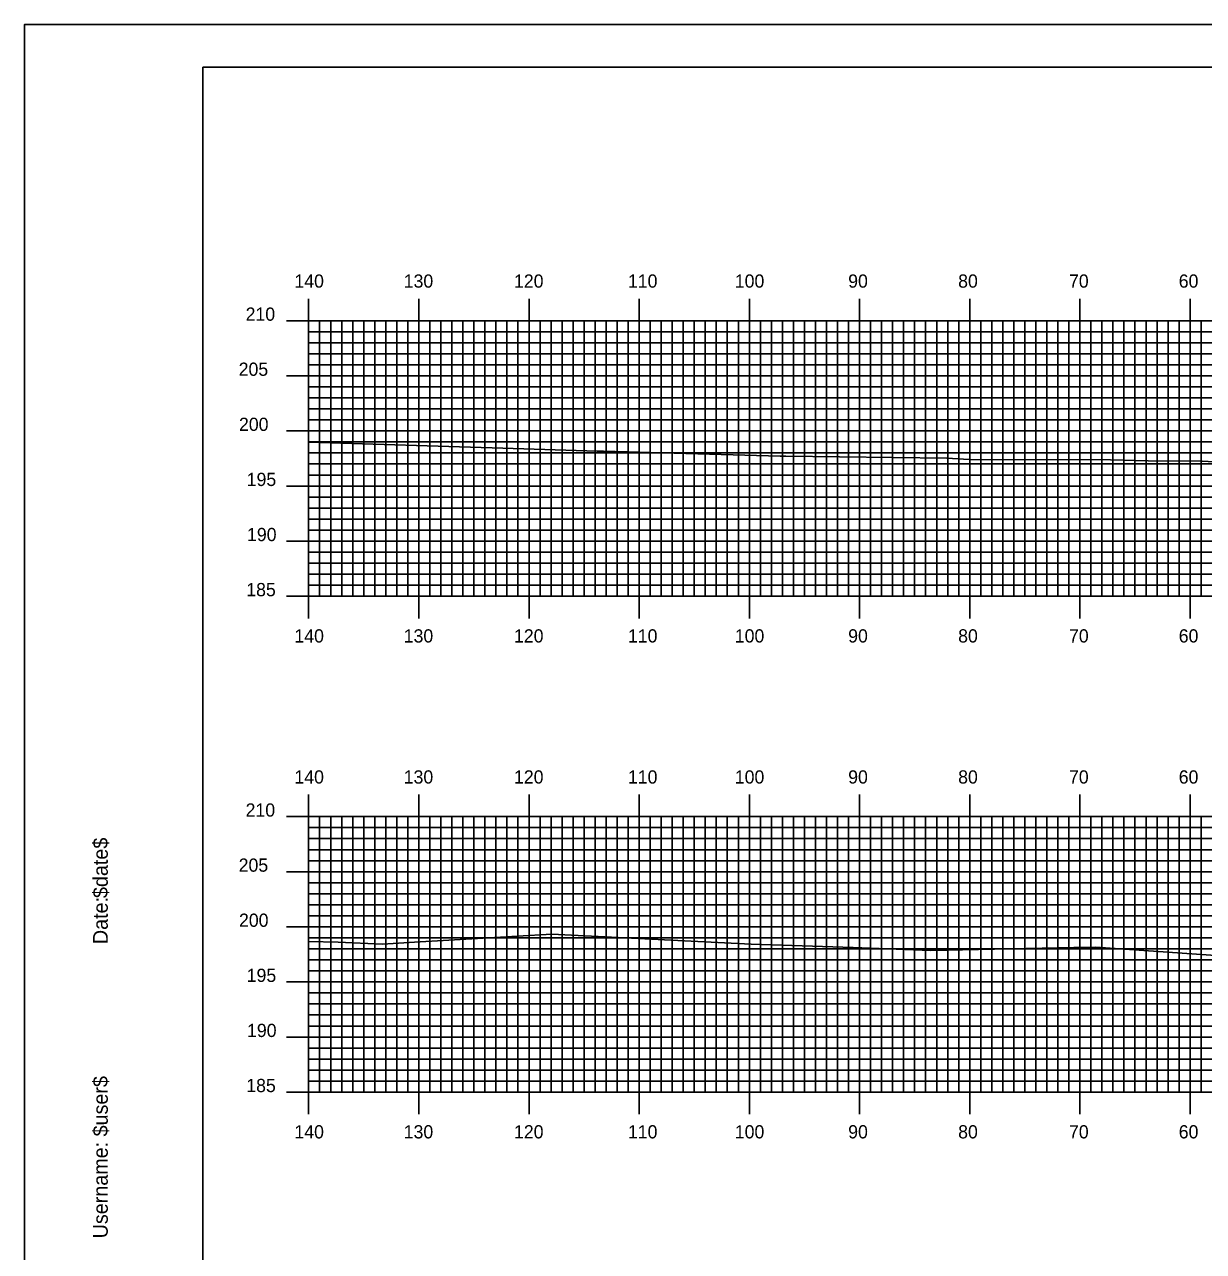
# Model space of a CAD drawing. Extents: x 1813735 to 1814078, y 442591 to 442811.
# Drawn here: x 1813734.7 to 1813841.7, y 442699.2 to 442810.5 of the extents above; entities that cross this region are included whole.
import ezdxf

# ---------------------------------------------------------------- set-up
doc = ezdxf.new("R2010")
doc.units = 0
for name, color, linetype in [('BORDER', 7, 'Continuous'), ('H_V ANNOTATION', 7, 'Continuous'), ('MAJOR', 7, 'Continuous'), ('MINOR', 7, 'Continuous'), ('PLOT BOUNDARY', 7, 'Continuous'), ('S_Roadway_Centerline', 7, 'Continuous')]:
    doc.layers.add(name, color=color, linetype=linetype)

msp = doc.modelspace()

# ---------------------------------------------------------------- linework, layer by layer
at = {"layer": 'BORDER'}
msp.add_lwpolyline([(1813750.88, 442596.67), (1814070.88, 442596.67), (1814070.88, 442806.67), (1813750.88, 442806.67)], close=True, dxfattribs=at)
at = {"layer": 'MAJOR'}
for p, q in [((1813760.48, 442785.67), (1813760.48, 442783.67)), ((1813770.48, 442785.67), (1813770.48, 442783.67)), ((1813780.48, 442785.67), (1813780.48, 442783.67)), ((1813790.48, 442785.67), (1813790.48, 442783.67)), ((1813800.48, 442785.67), (1813800.48, 442783.67)), ((1813810.48, 442785.67), (1813810.48, 442783.67)), ((1813820.48, 442785.67), (1813820.48, 442783.67)), ((1813830.48, 442785.67), (1813830.48, 442783.67)), ((1813840.48, 442785.67), (1813840.48, 442783.67)), ((1813758.48, 442783.67), (1813760.48, 442783.67)), ((1813760.48, 442783.67), (1814040.48, 442783.67)), ((1813760.48, 442758.67), (1813760.48, 442783.67)), ((1813760.48, 442758.67), (1813760.48, 442783.67)), ((1813760.48, 442783.67), (1814040.48, 442783.67)), ((1813770.48, 442758.67), (1813770.48, 442783.67)), ((1813780.48, 442758.67), (1813780.48, 442783.67)), ((1813790.48, 442758.67), (1813790.48, 442783.67)), ((1813800.48, 442758.67), (1813800.48, 442783.67)), ((1813810.48, 442758.67), (1813810.48, 442783.67)), ((1813820.48, 442758.67), (1813820.48, 442783.67)), ((1813830.48, 442758.67), (1813830.48, 442783.67)), ((1813840.48, 442758.67), (1813840.48, 442783.67)), ((1813758.48, 442778.67), (1813760.48, 442778.67)), ((1813760.48, 442778.67), (1814040.48, 442778.67)), ((1813758.48, 442773.67), (1813760.48, 442773.67)), ((1813760.48, 442773.67), (1814040.48, 442773.67)), ((1813758.48, 442768.67), (1813760.48, 442768.67)), ((1813760.48, 442768.67), (1814040.48, 442768.67)), ((1813758.48, 442763.67), (1813760.48, 442763.67)), ((1813760.48, 442763.67), (1814040.48, 442763.67)), ((1813758.48, 442758.67), (1813760.48, 442758.67)), ((1813760.48, 442758.67), (1814040.48, 442758.67)), ((1813760.48, 442758.67), (1814040.48, 442758.67)), ((1813760.48, 442756.66), (1813760.48, 442758.67)), ((1813770.48, 442756.66), (1813770.48, 442758.67)), ((1813780.48, 442756.66), (1813780.48, 442758.67)), ((1813790.48, 442756.66), (1813790.48, 442758.67)), ((1813800.48, 442756.66), (1813800.48, 442758.67)), ((1813810.48, 442756.66), (1813810.48, 442758.67)), ((1813820.48, 442756.66), (1813820.48, 442758.67)), ((1813830.48, 442756.66), (1813830.48, 442758.67)), ((1813840.48, 442756.66), (1813840.48, 442758.67)), ((1813760.48, 442740.67), (1813760.48, 442738.67)), ((1813770.48, 442740.67), (1813770.48, 442738.67)), ((1813780.48, 442740.67), (1813780.48, 442738.67)), ((1813790.48, 442740.67), (1813790.48, 442738.67)), ((1813800.48, 442740.67), (1813800.48, 442738.67)), ((1813810.48, 442740.67), (1813810.48, 442738.67)), ((1813820.48, 442740.67), (1813820.48, 442738.67)), ((1813830.48, 442740.67), (1813830.48, 442738.67)), ((1813840.48, 442740.67), (1813840.48, 442738.67)), ((1813758.48, 442738.67), (1813760.48, 442738.67)), ((1813760.48, 442738.67), (1814040.48, 442738.67)), ((1813760.48, 442713.67), (1813760.48, 442738.67)), ((1813760.48, 442713.67), (1813760.48, 442738.67)), ((1813760.48, 442738.67), (1814040.48, 442738.67)), ((1813770.48, 442713.67), (1813770.48, 442738.67)), ((1813780.48, 442713.67), (1813780.48, 442738.67)), ((1813790.48, 442713.67), (1813790.48, 442738.67)), ((1813800.48, 442713.67), (1813800.48, 442738.67)), ((1813810.48, 442713.67), (1813810.48, 442738.67)), ((1813820.48, 442713.67), (1813820.48, 442738.67)), ((1813830.48, 442713.67), (1813830.48, 442738.67)), ((1813840.48, 442713.67), (1813840.48, 442738.67)), ((1813758.48, 442733.67), (1813760.48, 442733.67)), ((1813760.48, 442733.67), (1814040.48, 442733.67)), ((1813758.48, 442728.67), (1813760.48, 442728.67)), ((1813760.48, 442728.67), (1814040.48, 442728.67)), ((1813758.48, 442723.67), (1813760.48, 442723.67)), ((1813760.48, 442723.67), (1814040.48, 442723.67)), ((1813758.48, 442718.67), (1813760.48, 442718.67)), ((1813760.48, 442718.67), (1814040.48, 442718.67)), ((1813758.48, 442713.67), (1813760.48, 442713.67)), ((1813760.48, 442713.67), (1814040.48, 442713.67)), ((1813760.48, 442713.67), (1814040.48, 442713.67)), ((1813760.48, 442711.66), (1813760.48, 442713.67)), ((1813770.48, 442711.66), (1813770.48, 442713.67)), ((1813780.48, 442711.66), (1813780.48, 442713.67)), ((1813790.48, 442711.66), (1813790.48, 442713.67)), ((1813800.48, 442711.66), (1813800.48, 442713.67)), ((1813810.48, 442711.66), (1813810.48, 442713.67)), ((1813820.48, 442711.66), (1813820.48, 442713.67)), ((1813830.48, 442711.66), (1813830.48, 442713.67)), ((1813840.48, 442711.66), (1813840.48, 442713.67))]:
    msp.add_line(p, q, dxfattribs=at)
at = {"layer": 'MINOR'}
for p, q in [((1813761.48, 442758.67), (1813761.48, 442783.67)), ((1813762.48, 442758.67), (1813762.48, 442783.67)), ((1813763.48, 442758.67), (1813763.48, 442783.67)), ((1813764.48, 442758.67), (1813764.48, 442783.67)), ((1813765.48, 442758.67), (1813765.48, 442783.67)), ((1813766.48, 442758.67), (1813766.48, 442783.67)), ((1813767.48, 442758.67), (1813767.48, 442783.67)), ((1813768.48, 442758.67), (1813768.48, 442783.67)), ((1813769.48, 442758.67), (1813769.48, 442783.67)), ((1813771.48, 442758.67), (1813771.48, 442783.67)), ((1813772.48, 442758.67), (1813772.48, 442783.67)), ((1813773.48, 442758.67), (1813773.48, 442783.67)), ((1813774.48, 442758.67), (1813774.48, 442783.67)), ((1813775.48, 442758.67), (1813775.48, 442783.67)), ((1813776.48, 442758.67), (1813776.48, 442783.67)), ((1813777.48, 442758.67), (1813777.48, 442783.67)), ((1813778.48, 442758.67), (1813778.48, 442783.67)), ((1813779.48, 442758.67), (1813779.48, 442783.67)), ((1813781.48, 442758.67), (1813781.48, 442783.67)), ((1813782.48, 442758.67), (1813782.48, 442783.67)), ((1813783.48, 442758.67), (1813783.48, 442783.67)), ((1813784.48, 442758.67), (1813784.48, 442783.67)), ((1813785.48, 442758.67), (1813785.48, 442783.67)), ((1813786.48, 442758.67), (1813786.48, 442783.67)), ((1813787.48, 442758.67), (1813787.48, 442783.67)), ((1813788.48, 442758.67), (1813788.48, 442783.67)), ((1813789.48, 442758.67), (1813789.48, 442783.67)), ((1813791.48, 442758.67), (1813791.48, 442783.67)), ((1813792.48, 442758.67), (1813792.48, 442783.67)), ((1813793.48, 442758.67), (1813793.48, 442783.67)), ((1813794.48, 442758.67), (1813794.48, 442783.67)), ((1813795.48, 442758.67), (1813795.48, 442783.67)), ((1813796.48, 442758.67), (1813796.48, 442783.67)), ((1813797.48, 442758.67), (1813797.48, 442783.67)), ((1813798.48, 442758.67), (1813798.48, 442783.67)), ((1813799.48, 442758.67), (1813799.48, 442783.67)), ((1813801.48, 442758.67), (1813801.48, 442783.67)), ((1813802.48, 442758.67), (1813802.48, 442783.67)), ((1813803.48, 442758.67), (1813803.48, 442783.67)), ((1813804.48, 442758.67), (1813804.48, 442783.67)), ((1813805.48, 442758.67), (1813805.48, 442783.67)), ((1813806.48, 442758.67), (1813806.48, 442783.67)), ((1813807.48, 442758.67), (1813807.48, 442783.67)), ((1813808.48, 442758.67), (1813808.48, 442783.67)), ((1813809.48, 442758.67), (1813809.48, 442783.67)), ((1813811.48, 442758.67), (1813811.48, 442783.67)), ((1813812.48, 442758.67), (1813812.48, 442783.67)), ((1813813.48, 442758.67), (1813813.48, 442783.67)), ((1813814.48, 442758.67), (1813814.48, 442783.67)), ((1813815.48, 442758.67), (1813815.48, 442783.67)), ((1813816.48, 442758.67), (1813816.48, 442783.67)), ((1813817.48, 442758.67), (1813817.48, 442783.67)), ((1813818.48, 442758.67), (1813818.48, 442783.67)), ((1813819.48, 442758.67), (1813819.48, 442783.67)), ((1813821.48, 442758.67), (1813821.48, 442783.67)), ((1813822.48, 442758.67), (1813822.48, 442783.67)), ((1813823.48, 442758.67), (1813823.48, 442783.67)), ((1813824.48, 442758.67), (1813824.48, 442783.67)), ((1813825.48, 442758.67), (1813825.48, 442783.67)), ((1813826.48, 442758.67), (1813826.48, 442783.67)), ((1813827.48, 442758.67), (1813827.48, 442783.67)), ((1813828.48, 442758.67), (1813828.48, 442783.67)), ((1813829.48, 442758.67), (1813829.48, 442783.67)), ((1813831.48, 442758.67), (1813831.48, 442783.67)), ((1813832.48, 442758.67), (1813832.48, 442783.67)), ((1813833.48, 442758.67), (1813833.48, 442783.67)), ((1813834.48, 442758.67), (1813834.48, 442783.67)), ((1813835.48, 442758.67), (1813835.48, 442783.67)), ((1813836.48, 442758.67), (1813836.48, 442783.67)), ((1813837.48, 442758.67), (1813837.48, 442783.67)), ((1813838.48, 442758.67), (1813838.48, 442783.67)), ((1813839.48, 442758.67), (1813839.48, 442783.67)), ((1813841.48, 442758.67), (1813841.48, 442783.67)), ((1813760.48, 442782.67), (1814040.48, 442782.67)), ((1813760.48, 442782.67), (1813762.49, 442782.67)), ((1813760.48, 442781.67), (1814040.48, 442781.67)), ((1813760.48, 442781.67), (1813762.49, 442781.67)), ((1813760.48, 442780.67), (1814040.48, 442780.67)), ((1813760.48, 442780.67), (1813762.49, 442780.67)), ((1813760.48, 442779.67), (1814040.48, 442779.67)), ((1813760.48, 442779.67), (1813762.49, 442779.67)), ((1813760.48, 442777.67), (1814040.48, 442777.67)), ((1813760.48, 442777.67), (1813762.49, 442777.67)), ((1813760.48, 442776.67), (1814040.48, 442776.67)), ((1813760.48, 442776.67), (1813762.49, 442776.67)), ((1813760.48, 442775.67), (1814040.48, 442775.67)), ((1813760.48, 442775.67), (1813762.49, 442775.67)), ((1813760.48, 442774.67), (1814040.48, 442774.67)), ((1813760.48, 442774.67), (1813762.49, 442774.67)), ((1813760.48, 442772.67), (1814040.48, 442772.67)), ((1813760.48, 442772.67), (1813762.49, 442772.67)), ((1813760.48, 442771.67), (1814040.48, 442771.67)), ((1813760.48, 442771.67), (1813762.49, 442771.67)), ((1813760.48, 442770.67), (1814040.48, 442770.67)), ((1813760.48, 442770.67), (1813762.49, 442770.67)), ((1813760.48, 442769.67), (1814040.48, 442769.67)), ((1813760.48, 442769.67), (1813762.49, 442769.67)), ((1813760.48, 442767.67), (1814040.48, 442767.67)), ((1813760.48, 442767.67), (1813762.49, 442767.67)), ((1813760.48, 442766.67), (1814040.48, 442766.67)), ((1813760.48, 442766.67), (1813762.49, 442766.67)), ((1813760.48, 442765.67), (1814040.48, 442765.67)), ((1813760.48, 442765.67), (1813762.49, 442765.67)), ((1813760.48, 442764.67), (1814040.48, 442764.67)), ((1813760.48, 442764.67), (1813762.49, 442764.67)), ((1813760.48, 442762.67), (1814040.48, 442762.67)), ((1813760.48, 442762.67), (1813762.49, 442762.67)), ((1813760.48, 442761.67), (1814040.48, 442761.67)), ((1813760.48, 442761.67), (1813762.49, 442761.67)), ((1813760.48, 442760.67), (1814040.48, 442760.67)), ((1813760.48, 442760.67), (1813762.49, 442760.67)), ((1813760.48, 442759.67), (1814040.48, 442759.67)), ((1813760.48, 442759.67), (1813762.49, 442759.67)), ((1813761.48, 442713.67), (1813761.48, 442738.67)), ((1813762.48, 442713.67), (1813762.48, 442738.67)), ((1813763.48, 442713.67), (1813763.48, 442738.67)), ((1813764.48, 442713.67), (1813764.48, 442738.67)), ((1813765.48, 442713.67), (1813765.48, 442738.67)), ((1813766.48, 442713.67), (1813766.48, 442738.67)), ((1813767.48, 442713.67), (1813767.48, 442738.67)), ((1813768.48, 442713.67), (1813768.48, 442738.67)), ((1813769.48, 442713.67), (1813769.48, 442738.67)), ((1813771.48, 442713.67), (1813771.48, 442738.67)), ((1813772.48, 442713.67), (1813772.48, 442738.67)), ((1813773.48, 442713.67), (1813773.48, 442738.67)), ((1813774.48, 442713.67), (1813774.48, 442738.67)), ((1813775.48, 442713.67), (1813775.48, 442738.67)), ((1813776.48, 442713.67), (1813776.48, 442738.67)), ((1813777.48, 442713.67), (1813777.48, 442738.67)), ((1813778.48, 442713.67), (1813778.48, 442738.67)), ((1813779.48, 442713.67), (1813779.48, 442738.67)), ((1813781.48, 442713.67), (1813781.48, 442738.67)), ((1813782.48, 442713.67), (1813782.48, 442738.67)), ((1813783.48, 442713.67), (1813783.48, 442738.67)), ((1813784.48, 442713.67), (1813784.48, 442738.67)), ((1813785.48, 442713.67), (1813785.48, 442738.67)), ((1813786.48, 442713.67), (1813786.48, 442738.67)), ((1813787.48, 442713.67), (1813787.48, 442738.67)), ((1813788.48, 442713.67), (1813788.48, 442738.67)), ((1813789.48, 442713.67), (1813789.48, 442738.67)), ((1813791.48, 442713.67), (1813791.48, 442738.67)), ((1813792.48, 442713.67), (1813792.48, 442738.67)), ((1813793.48, 442713.67), (1813793.48, 442738.67)), ((1813794.48, 442713.67), (1813794.48, 442738.67)), ((1813795.48, 442713.67), (1813795.48, 442738.67)), ((1813796.48, 442713.67), (1813796.48, 442738.67)), ((1813797.48, 442713.67), (1813797.48, 442738.67)), ((1813798.48, 442713.67), (1813798.48, 442738.67)), ((1813799.48, 442713.67), (1813799.48, 442738.67)), ((1813801.48, 442713.67), (1813801.48, 442738.67)), ((1813802.48, 442713.67), (1813802.48, 442738.67)), ((1813803.48, 442713.67), (1813803.48, 442738.67)), ((1813804.48, 442713.67), (1813804.48, 442738.67)), ((1813805.48, 442713.67), (1813805.48, 442738.67)), ((1813806.48, 442713.67), (1813806.48, 442738.67)), ((1813807.48, 442713.67), (1813807.48, 442738.67)), ((1813808.48, 442713.67), (1813808.48, 442738.67)), ((1813809.48, 442713.67), (1813809.48, 442738.67)), ((1813811.48, 442713.67), (1813811.48, 442738.67)), ((1813812.48, 442713.67), (1813812.48, 442738.67)), ((1813813.48, 442713.67), (1813813.48, 442738.67)), ((1813814.48, 442713.67), (1813814.48, 442738.67)), ((1813815.48, 442713.67), (1813815.48, 442738.67)), ((1813816.48, 442713.67), (1813816.48, 442738.67)), ((1813817.48, 442713.67), (1813817.48, 442738.67)), ((1813818.48, 442713.67), (1813818.48, 442738.67)), ((1813819.48, 442713.67), (1813819.48, 442738.67)), ((1813821.48, 442713.67), (1813821.48, 442738.67)), ((1813822.48, 442713.67), (1813822.48, 442738.67)), ((1813823.48, 442713.67), (1813823.48, 442738.67)), ((1813824.48, 442713.67), (1813824.48, 442738.67)), ((1813825.48, 442713.67), (1813825.48, 442738.67)), ((1813826.48, 442713.67), (1813826.48, 442738.67)), ((1813827.48, 442713.67), (1813827.48, 442738.67)), ((1813828.48, 442713.67), (1813828.48, 442738.67)), ((1813829.48, 442713.67), (1813829.48, 442738.67)), ((1813831.48, 442713.67), (1813831.48, 442738.67)), ((1813832.48, 442713.67), (1813832.48, 442738.67)), ((1813833.48, 442713.67), (1813833.48, 442738.67)), ((1813834.48, 442713.67), (1813834.48, 442738.67)), ((1813835.48, 442713.67), (1813835.48, 442738.67)), ((1813836.48, 442713.67), (1813836.48, 442738.67)), ((1813837.48, 442713.67), (1813837.48, 442738.67)), ((1813838.48, 442713.67), (1813838.48, 442738.67)), ((1813839.48, 442713.67), (1813839.48, 442738.67)), ((1813841.48, 442713.67), (1813841.48, 442738.67)), ((1813760.48, 442737.67), (1814040.48, 442737.67)), ((1813760.48, 442737.67), (1813762.49, 442737.67)), ((1813760.48, 442736.67), (1814040.48, 442736.67)), ((1813760.48, 442736.67), (1813762.49, 442736.67)), ((1813760.48, 442735.67), (1814040.48, 442735.67)), ((1813760.48, 442735.67), (1813762.49, 442735.67)), ((1813760.48, 442734.67), (1814040.48, 442734.67)), ((1813760.48, 442734.67), (1813762.49, 442734.67)), ((1813760.48, 442732.67), (1814040.48, 442732.67)), ((1813760.48, 442732.67), (1813762.49, 442732.67)), ((1813760.48, 442731.67), (1814040.48, 442731.67)), ((1813760.48, 442731.67), (1813762.49, 442731.67)), ((1813760.48, 442730.67), (1814040.48, 442730.67)), ((1813760.48, 442730.67), (1813762.49, 442730.67)), ((1813760.48, 442729.67), (1814040.48, 442729.67)), ((1813760.48, 442729.67), (1813762.49, 442729.67)), ((1813760.48, 442727.67), (1814040.48, 442727.67)), ((1813760.48, 442727.67), (1813762.49, 442727.67)), ((1813760.48, 442726.67), (1814040.48, 442726.67)), ((1813760.48, 442726.67), (1813762.49, 442726.67)), ((1813760.48, 442725.67), (1814040.48, 442725.67)), ((1813760.48, 442725.67), (1813762.49, 442725.67)), ((1813760.48, 442724.67), (1814040.48, 442724.67)), ((1813760.48, 442724.67), (1813762.49, 442724.67)), ((1813760.48, 442722.67), (1814040.48, 442722.67)), ((1813760.48, 442722.67), (1813762.49, 442722.67)), ((1813760.48, 442721.67), (1814040.48, 442721.67)), ((1813760.48, 442721.67), (1813762.49, 442721.67)), ((1813760.48, 442720.67), (1814040.48, 442720.67)), ((1813760.48, 442720.67), (1813762.49, 442720.67)), ((1813760.48, 442719.67), (1814040.48, 442719.67)), ((1813760.48, 442719.67), (1813762.49, 442719.67)), ((1813760.48, 442717.67), (1814040.48, 442717.67)), ((1813760.48, 442717.67), (1813762.49, 442717.67)), ((1813760.48, 442716.67), (1814040.48, 442716.67)), ((1813760.48, 442716.67), (1813762.49, 442716.67)), ((1813760.48, 442715.67), (1814040.48, 442715.67)), ((1813760.48, 442715.67), (1813762.49, 442715.67)), ((1813760.48, 442714.67), (1814040.48, 442714.67)), ((1813760.48, 442714.67), (1813762.49, 442714.67))]:
    msp.add_line(p, q, dxfattribs=at)
at = {"layer": 'PLOT BOUNDARY'}
msp.add_lwpolyline([(1813734.69, 442590.55), (1814074.69, 442590.55), (1814074.69, 442810.55), (1813734.69, 442810.55)], close=True, dxfattribs=at)
at = {"layer": 'S_Roadway_Centerline'}
for points in [[(1813760.48, 442772.66), (1813778.12, 442772.11), (1813786.67, 442771.82), (1813787.25, 442771.82), (1813803.28, 442771.39), (1813803.78, 442771.39), (1813818.39, 442771.2), (1813820.44, 442771.08), (1813833.26, 442771.04), (1813836.69, 442770.97), (1813841.59, 442770.94), (1813854.06, 442770.23), (1813865.61, 442769.74), (1813886.64, 442769.16), (1813894.36, 442769.16), (1813901.59, 442768.95), (1813909.64, 442768.51), (1813918.85, 442768.27), (1813927.99, 442768.02), (1813934.7, 442767.83), (1813945.69, 442767.6), (1813951.79, 442767.46), (1813956.33, 442767.23), (1813968.35, 442766.36)], [(1813760.48, 442727.35), (1813763.16, 442727.27), (1813767.18, 442727.1), (1813770.09, 442727.27), (1813782.54, 442728), (1813784.34, 442727.9), (1813800.63, 442727.09), (1813809.91, 442726.78), (1813816.96, 442726.52), (1813829.93, 442726.8), (1813831.93, 442726.82), (1813846.29, 442725.84)]]:
    msp.add_lwpolyline(points, dxfattribs=at)

# ---------------------------------------------------------------- texts
at = {"layer": 'BORDER'}
for s, p in [('$date$', (1813742.25, 442731.28)), ('Date:', (1813742.25, 442727.1)), ('$user$', (1813742.25, 442709.65)), ('Username:', (1813742.25, 442700.4))]:
    msp.add_text(s, height=1.339, rotation=90, dxfattribs=at).set_placement(p)
at = {"layer": 'H_V ANNOTATION'}
for s, p in [('140', (1813759.19, 442786.67)), ('130', (1813769.11, 442786.67)), ('120', (1813779.12, 442786.67)), ('110', (1813789.46, 442786.67)), ('100', (1813799.16, 442786.67)), ('90', (1813809.45, 442786.67)), ('80', (1813819.43, 442786.67)), ('70', (1813829.49, 442786.67)), ('60', (1813839.45, 442786.67)), ('210', (1813754.76, 442783.67)), ('205', (1813754.13, 442778.67)), ('200', (1813754.16, 442773.67)), ('195', (1813754.86, 442768.67)), ('190', (1813754.89, 442763.67)), ('185', (1813754.82, 442758.67)), ('140', (1813759.19, 442754.47)), ('130', (1813769.11, 442754.47)), ('120', (1813779.12, 442754.47)), ('110', (1813789.46, 442754.47)), ('100', (1813799.16, 442754.47)), ('90', (1813809.45, 442754.47)), ('80', (1813819.43, 442754.47)), ('70', (1813829.49, 442754.47)), ('60', (1813839.45, 442754.47)), ('140', (1813759.19, 442741.67)), ('130', (1813769.11, 442741.67)), ('120', (1813779.12, 442741.67)), ('110', (1813789.46, 442741.67)), ('100', (1813799.16, 442741.67)), ('90', (1813809.45, 442741.67)), ('80', (1813819.43, 442741.67)), ('70', (1813829.49, 442741.67)), ('60', (1813839.45, 442741.67)), ('210', (1813754.76, 442738.67)), ('205', (1813754.13, 442733.67)), ('200', (1813754.16, 442728.67)), ('195', (1813754.86, 442723.67)), ('190', (1813754.89, 442718.67)), ('185', (1813754.82, 442713.67)), ('140', (1813759.19, 442709.47)), ('130', (1813769.11, 442709.47)), ('120', (1813779.12, 442709.47)), ('110', (1813789.46, 442709.47)), ('100', (1813799.16, 442709.47)), ('90', (1813809.45, 442709.47)), ('80', (1813819.43, 442709.47)), ('70', (1813829.49, 442709.47)), ('60', (1813839.45, 442709.47))]:
    msp.add_text(s, height=1.2, dxfattribs=at).set_placement(p)
at = {"layer": 'MAJOR'}
for p in [(1813760.47, 442758.67), (1813760.47, 442713.67)]:
    msp.add_text('-', height=0.012, dxfattribs=at).set_placement(p)

doc.saveas('drawing.dxf')
